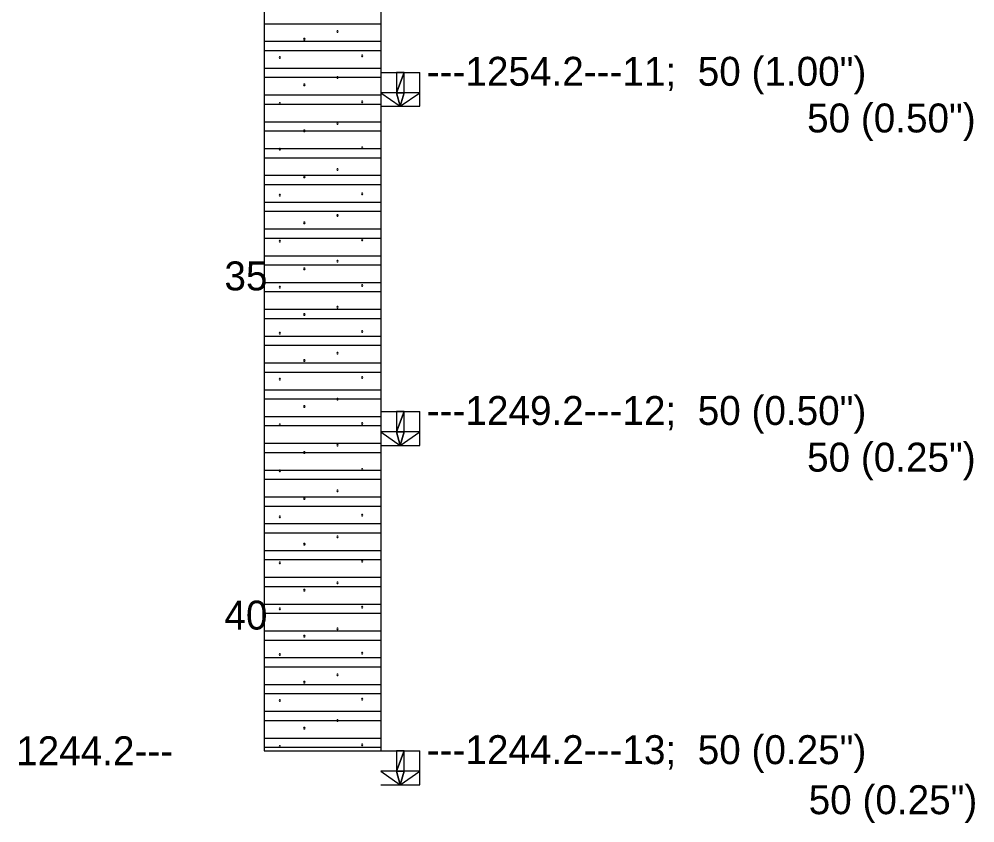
# Model space of a CAD drawing. Extents: x -6 to 173, y 24 to 64.
# Drawn here: x 17.255 to 21.351, y 36.874 to 40.318 of the extents above; entities that cross this region are included whole.
import ezdxf

# ---------------------------------------------------------------- set-up
doc = ezdxf.new("R2010")
doc.units = 0

msp = doc.modelspace()

# ---------------------------------------------------------------- linework, layer by layer
for points in [[(18.3057, 49.3922), (18.3057, 37.1829)], [(18.8057, 49.3922), (18.8057, 37.1829)], [(18.3057, 40.2986), (18.8057, 40.2986)], [(18.6233, 40.2648), (18.6217, 40.2676), (18.6184, 40.2676), (18.6167, 40.2648), (18.6184, 40.2619), (18.6217, 40.2619), (18.6233, 40.2648)], [(18.3057, 40.2231), (18.8057, 40.2231)], [(18.4807, 40.2329), (18.4791, 40.2358), (18.4758, 40.2358), (18.4742, 40.2329), (18.4758, 40.2301), (18.4791, 40.2301), (18.4807, 40.2329)], [(18.3057, 40.1837), (18.8057, 40.1837)], [(18.3761, 40.1539), (18.3744, 40.1568), (18.3711, 40.1568), (18.3695, 40.1539), (18.3711, 40.1511), (18.3744, 40.1511), (18.3761, 40.1539)], [(18.7288, 40.1604), (18.7272, 40.1633), (18.7239, 40.1633), (18.7223, 40.1604), (18.7239, 40.1576), (18.7272, 40.1576), (18.7288, 40.1604)], [(18.3057, 40.1083), (18.8057, 40.1083)], [(18.3057, 40.0689), (18.8057, 40.0689)], [(18.6233, 40.0679), (18.6217, 40.0707), (18.6184, 40.0707), (18.6167, 40.0679), (18.6184, 40.0651), (18.6217, 40.0651), (18.6233, 40.0679)], [(18.8057, 40.0899), (18.9723, 40.0899)], [(18.9723, 39.9445), (18.9723, 40.0899)], [(18.4807, 40.036), (18.4791, 40.0389), (18.4758, 40.0389), (18.4742, 40.0361), (18.4758, 40.0332), (18.4791, 40.0332), (18.4807, 40.036)], [(18.3057, 39.9934), (18.8057, 39.9934)], [(18.3057, 39.9541), (18.8057, 39.9541)], [(18.3761, 39.9571), (18.3744, 39.9599), (18.3711, 39.9599), (18.3695, 39.9571), (18.3711, 39.9542), (18.3744, 39.9542), (18.3761, 39.9571)], [(18.7288, 39.9636), (18.7272, 39.9665), (18.7239, 39.9665), (18.7223, 39.9636), (18.7239, 39.9608), (18.7272, 39.9608), (18.7288, 39.9636)], [(18.8057, 39.9445), (18.9723, 39.9445)], [(18.3057, 39.8786), (18.8057, 39.8786)], [(18.6233, 39.8711), (18.6217, 39.8739), (18.6184, 39.8739), (18.6167, 39.8711), (18.6184, 39.8682), (18.6217, 39.8682), (18.6233, 39.8711)], [(18.3057, 39.8392), (18.8057, 39.8392)], [(18.4807, 39.8392), (18.4791, 39.8421), (18.4758, 39.8421), (18.4742, 39.8392), (18.4758, 39.8364), (18.4791, 39.8364), (18.4807, 39.8392)], [(18.3057, 39.7638), (18.8057, 39.7638)], [(18.3761, 39.7602), (18.3744, 39.7631), (18.3711, 39.7631), (18.3695, 39.7602), (18.3711, 39.7574), (18.3744, 39.7574), (18.3761, 39.7602)], [(18.7288, 39.7667), (18.7272, 39.7696), (18.7239, 39.7696), (18.7223, 39.7667), (18.7239, 39.7639), (18.7272, 39.7639), (18.7288, 39.7667)], [(18.3057, 39.7244), (18.8057, 39.7244)], [(18.3057, 39.649), (18.8057, 39.649)], [(18.6233, 39.6742), (18.6217, 39.677), (18.6184, 39.677), (18.6167, 39.6742), (18.6184, 39.6714), (18.6217, 39.6714), (18.6233, 39.6742)], [(18.3057, 39.6096), (18.8057, 39.6096)], [(18.4807, 39.6423), (18.4791, 39.6452), (18.4758, 39.6452), (18.4742, 39.6424), (18.4758, 39.6395), (18.4791, 39.6395), (18.4807, 39.6423)], [(18.7288, 39.5699), (18.7272, 39.5728), (18.7239, 39.5728), (18.7223, 39.5699), (18.7239, 39.5671), (18.7272, 39.5671), (18.7288, 39.5699)], [(18.3057, 39.5341), (18.8057, 39.5341)], [(18.3761, 39.5634), (18.3744, 39.5662), (18.3711, 39.5662), (18.3695, 39.5634), (18.3711, 39.5605), (18.3744, 39.5605), (18.3761, 39.5634)], [(18.3057, 39.4948), (18.8057, 39.4948)], [(18.4807, 39.4455), (18.4791, 39.4484), (18.4758, 39.4484), (18.4742, 39.4455), (18.4758, 39.4427), (18.4791, 39.4427), (18.4807, 39.4455)], [(18.6233, 39.4774), (18.6217, 39.4802), (18.6184, 39.4802), (18.6167, 39.4774), (18.6184, 39.4745), (18.6217, 39.4745), (18.6233, 39.4774)], [(18.3057, 39.4193), (18.8057, 39.4193)], [(18.3057, 39.3799), (18.8057, 39.3799)], [(18.3761, 39.3665), (18.3744, 39.3694), (18.3711, 39.3694), (18.3695, 39.3665), (18.3711, 39.3637), (18.3744, 39.3637), (18.3761, 39.3665)], [(18.7288, 39.373), (18.7272, 39.3759), (18.7239, 39.3759), (18.7223, 39.373), (18.7239, 39.3702), (18.7272, 39.3702), (18.7288, 39.373)], [(18.3057, 39.3045), (18.8057, 39.3045)], [(18.6233, 39.2805), (18.6217, 39.2833), (18.6184, 39.2833), (18.6167, 39.2805), (18.6184, 39.2777), (18.6217, 39.2777), (18.6233, 39.2805)], [(18.3057, 39.2651), (18.8057, 39.2651)], [(18.4807, 39.2486), (18.4791, 39.2515), (18.4758, 39.2515), (18.4742, 39.2487), (18.4758, 39.2458), (18.4791, 39.2458), (18.4807, 39.2486)], [(18.3057, 39.1896), (18.8057, 39.1896)], [(18.3761, 39.1697), (18.3744, 39.1725), (18.3711, 39.1725), (18.3695, 39.1697), (18.3711, 39.1668), (18.3744, 39.1668), (18.3761, 39.1697)], [(18.7288, 39.1762), (18.7272, 39.1791), (18.7239, 39.1791), (18.7223, 39.1762), (18.7239, 39.1734), (18.7272, 39.1734), (18.7288, 39.1762)], [(18.3057, 39.1503), (18.8057, 39.1503)], [(18.6233, 39.0837), (18.6217, 39.0865), (18.6184, 39.0865), (18.6167, 39.0837), (18.6184, 39.0808), (18.6217, 39.0808), (18.6233, 39.0837)], [(18.3057, 39.0748), (18.8057, 39.0748)], [(18.3057, 39.0354), (18.8057, 39.0354)], [(18.4807, 39.0518), (18.4791, 39.0547), (18.4758, 39.0547), (18.4742, 39.0518), (18.4758, 39.049), (18.4791, 39.049), (18.4807, 39.0518)], [(18.3057, 38.96), (18.8057, 38.96)], [(18.3761, 38.9728), (18.3744, 38.9757), (18.3711, 38.9757), (18.3695, 38.9728), (18.3711, 38.97), (18.3744, 38.97), (18.3761, 38.9728)], [(18.7288, 38.9793), (18.7272, 38.9822), (18.7239, 38.9822), (18.7223, 38.9793), (18.7239, 38.9765), (18.7272, 38.9765), (18.7288, 38.9793)], [(18.3057, 38.9206), (18.8057, 38.9206)], [(18.6233, 38.8868), (18.6217, 38.8896), (18.6184, 38.8896), (18.6167, 38.8868), (18.6184, 38.884), (18.6217, 38.884), (18.6233, 38.8868)], [(18.3057, 38.8452), (18.8057, 38.8452)], [(18.4807, 38.8549), (18.4791, 38.8578), (18.4758, 38.8578), (18.4742, 38.855), (18.4758, 38.8521), (18.4791, 38.8521), (18.4807, 38.8549)], [(18.3057, 38.8058), (18.8057, 38.8058)], [(18.3761, 38.776), (18.3744, 38.7788), (18.3711, 38.7788), (18.3695, 38.776), (18.3711, 38.7731), (18.3744, 38.7731), (18.3761, 38.776)], [(18.7288, 38.7825), (18.7272, 38.7854), (18.7239, 38.7854), (18.7223, 38.7825), (18.7239, 38.7797), (18.7272, 38.7797), (18.7288, 38.7825)], [(18.3057, 38.7303), (18.8057, 38.7303)], [(18.3057, 38.691), (18.8057, 38.691)], [(18.6233, 38.69), (18.6217, 38.6928), (18.6184, 38.6928), (18.6167, 38.69), (18.6184, 38.6871), (18.6217, 38.6871), (18.6233, 38.69)], [(18.4807, 38.6581), (18.4791, 38.661), (18.4758, 38.661), (18.4742, 38.6581), (18.4758, 38.6553), (18.4791, 38.6553), (18.4807, 38.6581)], [(18.8057, 38.6364), (18.9723, 38.6364)], [(18.9723, 38.491), (18.9723, 38.6364)], [(18.3057, 38.6155), (18.8057, 38.6155)], [(18.7288, 38.5856), (18.7272, 38.5885), (18.7239, 38.5885), (18.7223, 38.5856), (18.7239, 38.5828), (18.7272, 38.5828), (18.7288, 38.5856)], [(18.3057, 38.5761), (18.8057, 38.5761)], [(18.3761, 38.5791), (18.3744, 38.582), (18.3711, 38.582), (18.3695, 38.5791), (18.3711, 38.5763), (18.3744, 38.5763), (18.3761, 38.5791)], [(18.3057, 38.5007), (18.8057, 38.5007)], [(18.3057, 38.4613), (18.8057, 38.4613)], [(18.4807, 38.4612), (18.4791, 38.4641), (18.4758, 38.4641), (18.4742, 38.4613), (18.4758, 38.4584), (18.4791, 38.4584), (18.4807, 38.4612)], [(18.6233, 38.4931), (18.6217, 38.4959), (18.6184, 38.4959), (18.6167, 38.4931), (18.6184, 38.4903), (18.6217, 38.4903), (18.6233, 38.4931)], [(18.8057, 38.491), (18.9723, 38.491)], [(18.3057, 38.3858), (18.8057, 38.3858)], [(18.3761, 38.3823), (18.3744, 38.3851), (18.3711, 38.3851), (18.3695, 38.3823), (18.3711, 38.3794), (18.3744, 38.3794), (18.3761, 38.3823)], [(18.7288, 38.3888), (18.7272, 38.3917), (18.7239, 38.3917), (18.7223, 38.3888), (18.7239, 38.386), (18.7272, 38.386), (18.7288, 38.3888)], [(18.3057, 38.3465), (18.8057, 38.3465)], [(18.6233, 38.2963), (18.6217, 38.2991), (18.6184, 38.2991), (18.6167, 38.2963), (18.6184, 38.2934), (18.6217, 38.2934), (18.6233, 38.2963)], [(18.3057, 38.271), (18.8057, 38.271)], [(18.4807, 38.2644), (18.4791, 38.2673), (18.4758, 38.2673), (18.4742, 38.2644), (18.4758, 38.2616), (18.4791, 38.2616), (18.4807, 38.2644)], [(18.3057, 38.2316), (18.8057, 38.2316)], [(18.3761, 38.1854), (18.3744, 38.1883), (18.3711, 38.1883), (18.3695, 38.1854), (18.3711, 38.1826), (18.3744, 38.1826), (18.3761, 38.1854)], [(18.7288, 38.1919), (18.7272, 38.1948), (18.7239, 38.1948), (18.7223, 38.1919), (18.7239, 38.1891), (18.7272, 38.1891), (18.7288, 38.1919)], [(18.3057, 38.1562), (18.8057, 38.1562)], [(18.3057, 38.1168), (18.8057, 38.1168)], [(18.6233, 38.0994), (18.6217, 38.1022), (18.6184, 38.1022), (18.6167, 38.0994), (18.6184, 38.0966), (18.6217, 38.0966), (18.6233, 38.0994)], [(18.4807, 38.0675), (18.4791, 38.0704), (18.4758, 38.0704), (18.4742, 38.0676), (18.4758, 38.0647), (18.4791, 38.0647), (18.4807, 38.0675)], [(18.3057, 38.0413), (18.8057, 38.0413)], [(18.3057, 38.002), (18.8057, 38.002)], [(18.3761, 37.9886), (18.3744, 37.9914), (18.3711, 37.9914), (18.3695, 37.9886), (18.3711, 37.9857), (18.3744, 37.9857), (18.3761, 37.9886)], [(18.7288, 37.9951), (18.7272, 37.998), (18.7239, 37.998), (18.7223, 37.9951), (18.7239, 37.9923), (18.7272, 37.9923), (18.7288, 37.9951)], [(18.3057, 37.9265), (18.8057, 37.9265)], [(18.3057, 37.8871), (18.8057, 37.8871)], [(18.6233, 37.9026), (18.6217, 37.9054), (18.6184, 37.9054), (18.6167, 37.9026), (18.6184, 37.8997), (18.6217, 37.8997), (18.6233, 37.9026)], [(18.4807, 37.8707), (18.4791, 37.8736), (18.4758, 37.8736), (18.4742, 37.8707), (18.4758, 37.8679), (18.4791, 37.8679), (18.4807, 37.8707)], [(18.3057, 37.8117), (18.8057, 37.8117)], [(18.3057, 37.7723), (18.8057, 37.7723)], [(18.3761, 37.7917), (18.3744, 37.7946), (18.3711, 37.7946), (18.3695, 37.7917), (18.3711, 37.7889), (18.3744, 37.7889), (18.3761, 37.7917)], [(18.7288, 37.7982), (18.7272, 37.8011), (18.7239, 37.8011), (18.7223, 37.7982), (18.7239, 37.7954), (18.7272, 37.7954), (18.7288, 37.7982)], [(18.3057, 37.6969), (18.8057, 37.6969)], [(18.6233, 37.7057), (18.6217, 37.7085), (18.6184, 37.7085), (18.6167, 37.7057), (18.6184, 37.7029), (18.6217, 37.7029), (18.6233, 37.7057)], [(18.3057, 37.6575), (18.8057, 37.6575)], [(18.4807, 37.6738), (18.4791, 37.6767), (18.4758, 37.6767), (18.4742, 37.6739), (18.4758, 37.671), (18.4791, 37.671), (18.4807, 37.6738)], [(18.7288, 37.6014), (18.7272, 37.6043), (18.7239, 37.6043), (18.7223, 37.6014), (18.7239, 37.5986), (18.7272, 37.5986), (18.7288, 37.6014)], [(18.3057, 37.582), (18.8057, 37.582)], [(18.3761, 37.5949), (18.3744, 37.5977), (18.3711, 37.5977), (18.3695, 37.5949), (18.3711, 37.592), (18.3744, 37.592), (18.3761, 37.5949)], [(18.3057, 37.5427), (18.8057, 37.5427)], [(18.4807, 37.477), (18.4791, 37.4799), (18.4758, 37.4799), (18.4742, 37.477), (18.4758, 37.4742), (18.4791, 37.4742), (18.4807, 37.477)], [(18.6233, 37.5089), (18.6217, 37.5117), (18.6184, 37.5117), (18.6167, 37.5089), (18.6184, 37.506), (18.6217, 37.506), (18.6233, 37.5089)], [(18.3057, 37.4672), (18.8057, 37.4672)], [(18.3057, 37.4278), (18.8057, 37.4278)], [(18.3761, 37.398), (18.3744, 37.4009), (18.3711, 37.4009), (18.3695, 37.398), (18.3711, 37.3952), (18.3744, 37.3952), (18.3761, 37.398)], [(18.7288, 37.4045), (18.7272, 37.4074), (18.7239, 37.4074), (18.7223, 37.4045), (18.7239, 37.4017), (18.7272, 37.4017), (18.7288, 37.4045)], [(18.3057, 37.3524), (18.8057, 37.3524)], [(18.6233, 37.312), (18.6217, 37.3148), (18.6184, 37.3148), (18.6167, 37.312), (18.6184, 37.3092), (18.6217, 37.3092), (18.6233, 37.312)], [(18.3057, 37.313), (18.8057, 37.313)], [(18.4807, 37.2801), (18.4791, 37.283), (18.4758, 37.283), (18.4742, 37.2802), (18.4758, 37.2773), (18.4791, 37.2773), (18.4807, 37.2801)], [(18.3057, 37.2375), (18.8057, 37.2375)], [(18.3057, 37.1982), (18.8057, 37.1982)], [(18.3761, 37.2012), (18.3744, 37.204), (18.3711, 37.204), (18.3695, 37.2012), (18.3711, 37.1983), (18.3744, 37.1983), (18.3761, 37.2012)], [(18.7288, 37.2077), (18.7272, 37.2106), (18.7239, 37.2106), (18.7223, 37.2077), (18.7239, 37.2049), (18.7272, 37.2049), (18.7288, 37.2077)], [(18.3057, 37.1829), (18.8057, 37.1829)], [(18.8057, 37.1829), (18.9723, 37.1829)], [(18.9723, 37.0375), (18.9723, 37.1829)], [(18.8057, 37.0375), (18.9723, 37.0375)]]:
    msp.add_lwpolyline(points)
for points in [[(18.8723, 40.0027), (18.9057, 40.0027), (18.9057, 40.0899), (18.8723, 40.0027)], [(18.8723, 40.0027), (18.9057, 40.0899), (18.8723, 40.0899), (18.8723, 40.0027)], [(18.8723, 40.0027), (18.8057, 40.0027), (18.889, 39.9445), (18.8723, 40.0027)], [(18.8723, 40.0027), (18.889, 39.9445), (18.9057, 40.0027), (18.8723, 40.0027)], [(18.889, 39.9445), (18.9723, 40.0027), (18.9057, 40.0027), (18.889, 39.9445)], [(18.8723, 38.5492), (18.9057, 38.5492), (18.9057, 38.6364), (18.8723, 38.5492)], [(18.8723, 38.5492), (18.9057, 38.6364), (18.8723, 38.6364), (18.8723, 38.5492)], [(18.8723, 38.5492), (18.8057, 38.5492), (18.889, 38.491), (18.8723, 38.5492)], [(18.8723, 38.5492), (18.889, 38.491), (18.9057, 38.5492), (18.8723, 38.5492)], [(18.889, 38.491), (18.9723, 38.5492), (18.9057, 38.5492), (18.889, 38.491)], [(18.8723, 37.0957), (18.9057, 37.0957), (18.9057, 37.1829), (18.8723, 37.0957)], [(18.8723, 37.0957), (18.9057, 37.1829), (18.8723, 37.1829), (18.8723, 37.0957)], [(18.8723, 37.0957), (18.8057, 37.0957), (18.889, 37.0375), (18.8723, 37.0957)], [(18.8723, 37.0957), (18.889, 37.0375), (18.9057, 37.0957), (18.8723, 37.0957)], [(18.889, 37.0375), (18.9723, 37.0957), (18.9057, 37.0957), (18.889, 37.0375)]]:
    msp.add_lwpolyline(points, close=True)

# ---------------------------------------------------------------- texts
for s, p in [('---1254.2---11;  50 (1.00")', (19.0024, 40.0326)), ('50 (0.50")', (20.6321, 39.8326)), ('35', (18.1352, 39.1558)), ('---1249.2---12;  50 (0.50")', (19.0024, 38.5791)), ('50 (0.25")', (20.6321, 38.3791)), ('40', (18.1352, 37.7023)), ('1244.2---', (17.2427, 37.1209)), ('---1244.2---13;  50 (0.25")', (19.0024, 37.1256)), ('50 (0.25")', (20.639, 36.9111))]:
    msp.add_text(s, height=0.124).set_placement(p)

doc.saveas('drawing.dxf')
